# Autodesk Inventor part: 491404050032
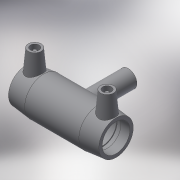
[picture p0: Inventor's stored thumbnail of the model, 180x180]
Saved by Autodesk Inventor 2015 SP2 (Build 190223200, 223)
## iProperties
Created: 2017-06
Part Number: 491404050032
Material: Generic
Description: PLASSON REDUCING TEE 50x32x50
Document SubType Name: Modeling
Designer: KIM
Mass: 57.3761 g
Surface Area: 241.06 cm^2
Volume: 57.3761 cm^3
Density: 1 g/cm^3
Appearance: Default
Author: KIM
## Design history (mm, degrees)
derived "491404.ipt"
feature "Solid1::491404.ipt"
tag "TaggingFeature1"
body "Solid1"
other parameters: "d0" = 139, "d2" = 68, "d3" = 48, "d4" = 27.8, "d5" = 61.2, "d6" = 47.5, "d8" = 168 deg, "d10" = 19.2, "d11" = 6.4, "d13" = 139, "d14" = 17.6296, "d17" = 45, "d19" = 3.52592, "d20" = 168 deg, "d22" = 63.24, "d23" = 68, "d25" = 135 deg, "d26" = 97.3, "d29" = 52, "d30" = 15, "d31" = 55.6, "d34" = 5 deg, "d35" = 15, "d39" = 5 deg, "d41" = 4, "d42" = 14, "d43" = 0, "d45" = 4, "d46" = 6, "d47" = 0, "d48" = -86, "d49" = 32, "d51" = 0, "d52" = 25.6, "d54" = 0, "d55" = 61.2, "d56" = 68, "d57" = 48.65, "d58" = 135 deg, "d59" = 48, "d60" = 48, "d61" = 135 deg, "d62" = 86, "d72" = 63.245, "d73" = 31.6225, "d74" = -86, "d75" = 33.6, "d77" = 0, "d78" = 25.6, "d80" = 0, "d81" = 32, "d82" = 52, "d83" = 0, "d84" = 3, "d85" = 0, "d86" = 16, "d87" = 61.9752, "d88" = 6.4, "d89" = 3, "d90" = 0, "L_" = 139, "L_1" = 48, "D_" = 68, "A_" = 52, "d_2" = 12, "H_" = 86, "d_1" = 32
